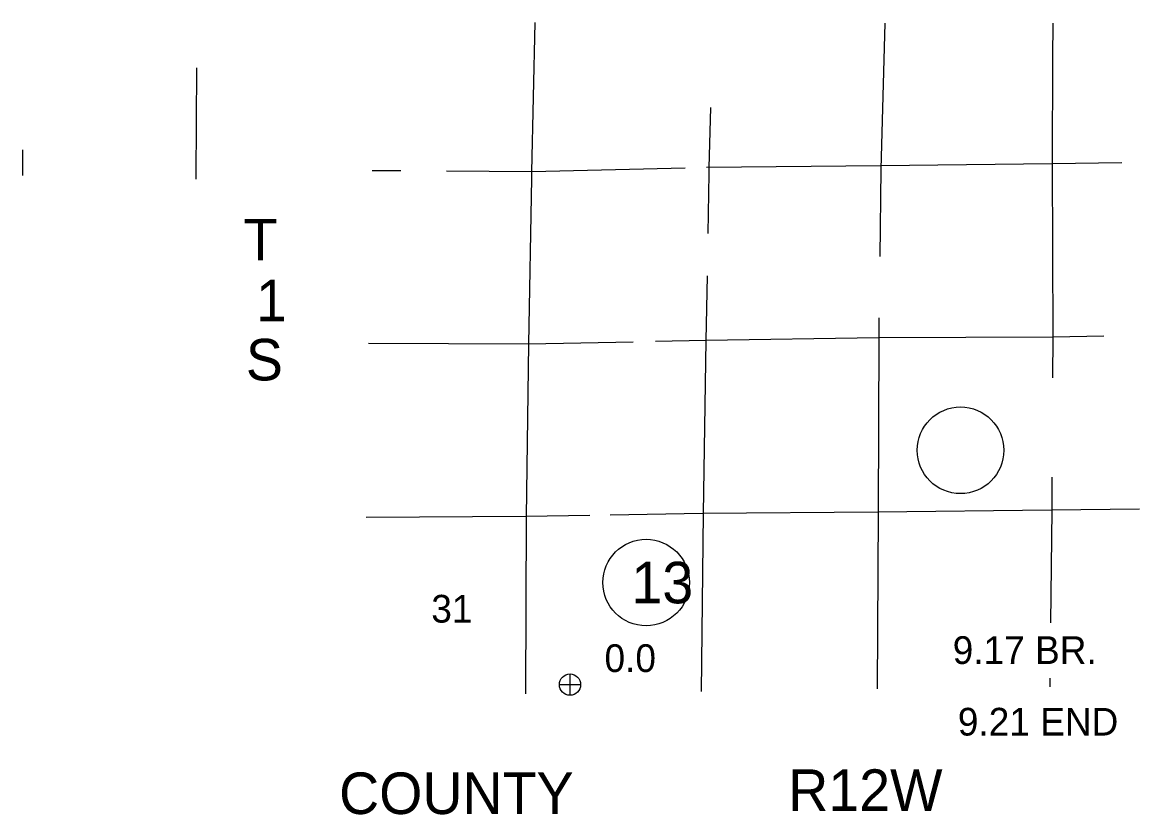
# Model space of a CAD drawing. Extents: x 1127717 to 1741049, y 2026793 to 2244711.
# Drawn here: x 1160984 to 1169507, y 2111668 to 2117709 of the extents above; entities that cross this region are included whole.
import ezdxf

# ---------------------------------------------------------------- set-up
doc = ezdxf.new("R2010")
doc.units = 0
for name, color, linetype in [('25', 7, 'Continuous'), ('26', 7, 'Continuous'), ('27', 7, 'Continuous'), ('30', 7, 'Continuous'), ('5', 7, 'Continuous'), ('58', 7, 'Continuous')]:
    doc.layers.add(name, color=color, linetype=linetype)

msp = doc.modelspace()

# ---------------------------------------------------------------- linework, layer by layer
at = {"layer": '26'}
for p, q in [((1165161.6, 2112578.6), (1165161.6, 2112741.1)), ((1165080.4, 2112659.8), (1165242.9, 2112659.8))]:
    msp.add_line(p, q, dxfattribs=at)
msp.add_circle((1165161.6, 2112659.8), 81.2, dxfattribs=at)
at = {"layer": '27'}
for centre in [(1168140.7, 2114446.2), (1165742.4, 2113437.6)]:
    msp.add_circle(centre, 330, dxfattribs=at)
at = {"layer": '5'}
for points in [[(1164894.2, 2117708.7), (1164868.4, 2116570.2), (1164868.5, 2116518.6)], [(1167564.3, 2117702.4), (1167532.6, 2116590.3)], [(1168843.9, 2117702.4), (1168842.8, 2117439.7)], [(1168842.8, 2117439.7), (1168839.5, 2116632.4)], [(1162312.6, 2117361.3), (1162308, 2116528.3), (1162307.8, 2116513)], [(1166233.1, 2117059.3), (1166221.3, 2116600.2), (1166221.3, 2116555.2)], [(1160984.7, 2116736.5), (1160983.6, 2116541.6)], [(1166203.1, 2116603.5), (1167534, 2116617.9), (1168839.5, 2116632.4)], [(1168839.5, 2116632.4), (1169371.3, 2116640)], [(1168839.5, 2116632.4), (1168844.2, 2115310.1), (1168842.5, 2114997.9)], [(1163652, 2116580.3), (1163870.5, 2116578.7)], [(1164220.2, 2116576.1), (1164869.4, 2116571.2), (1166039.8, 2116600.5)], [(1166221.3, 2116555.2), (1166213, 2116099.6)], [(1167532.6, 2116590.3), (1167524.2, 2115923.7)], [(1164868.5, 2116518.6), (1164845.5, 2115257.6), (1164826.2, 2113938.9), (1164822.4, 2112589.2)], [(1166207.1, 2115776.1), (1166198.2, 2115282.8), (1166176.4, 2113963.5), (1166162.8, 2112606.7)], [(1167518.3, 2115455.8), (1167516.4, 2115306.6), (1167512, 2113972.7), (1167505.8, 2112627.6)], [(1163625.6, 2115263.1), (1164845.5, 2115257.1), (1165644.3, 2115273.5)], [(1165813.3, 2115276.9), (1166197.6, 2115284.8), (1167516.9, 2115307.1), (1168844.2, 2115310.1), (1169233.7, 2115318.4)], [(1168838.3, 2114241.5), (1168836.9, 2113990.7), (1168827.5, 2113129.5)], [(1169507.4, 2113998.4), (1168834.9, 2113990.6), (1167511, 2113973.7), (1166175.9, 2113965), (1165469.2, 2113952.4)], [(1165311.7, 2113949.5), (1164823.7, 2113940.8), (1163605.6, 2113933.3)], [(1168822.9, 2112708.4), (1168822.2, 2112643.2)]]:
    msp.add_lwpolyline(points, dxfattribs=at)

# ---------------------------------------------------------------- texts
at = {"layer": '25'}
for s, p in [('0.0', (1165424.9, 2112755.8)), ('9.21 END', (1168120.3, 2112271.2))]:
    msp.add_text(s, height=211.2, dxfattribs=at).set_placement(p)
at = {"layer": '27'}
msp.add_text('13', height=316.8, dxfattribs=at).set_placement((1165630.2, 2113279.2))
at = {"layer": '30'}
for s, p in [('T', (1162671, 2115893.8)), ('1', (1162765.8, 2115429.2)), ('S', (1162689, 2114978.8)), ('COUNTY', (1163400.1, 2111672.8)), ('R12W', (1166826.3, 2111696.7))]:
    msp.add_text(s, height=316.8, dxfattribs=at).set_placement(p)
at = {"layer": '5'}
msp.add_text('31', height=211.2, dxfattribs=at).set_placement((1164103.4, 2113132.5))
at = {"layer": '58'}
msp.add_text('9.17 BR.', height=211.2, dxfattribs=at).set_placement((1168081.3, 2112817))

doc.saveas('drawing.dxf')
